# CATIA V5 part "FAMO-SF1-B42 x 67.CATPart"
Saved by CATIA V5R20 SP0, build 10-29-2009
Part number: FAMO-SF1-B42 x 67
Definition: NONE
Nomenclature: FAMO-SF1-B42 x 67
Source: Unknown
Description: FAMO-SF1-B42 x 67
Bounding box of the stored display mesh (mm): x -13 to 54, y -31.5 to 31.5, z -31.5 to 31.5
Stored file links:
  C:\Users\Utente\Desktop\IO LAVORO\3D X SITO CF\X SITO\FAMO\FAMO-SF1-B42 x 67.CATPart
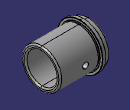
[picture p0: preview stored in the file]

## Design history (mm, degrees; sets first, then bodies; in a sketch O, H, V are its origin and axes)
Body1 "FAMO-SF1-B42 x 67" (main body)
  Solid1: solid without history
